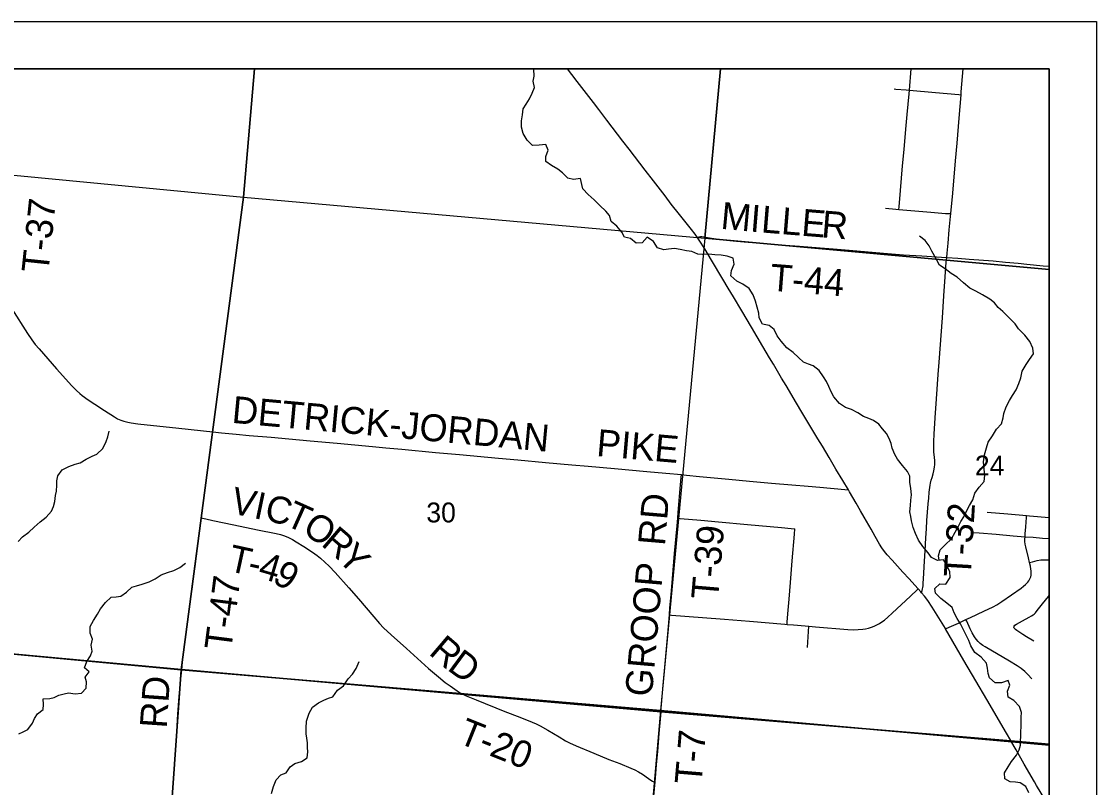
# Model space of a CAD drawing. Extents: x 831 to 1552, y 430 to 870.
# Drawn here: x 1343.42 to 1388.77, y 756.64 to 788.94 of the extents above; entities that cross this region are included whole.
import ezdxf

# ---------------------------------------------------------------- set-up
doc = ezdxf.new("R2010")
doc.units = 0
for name, color, linetype in [('GM_X_Corporation', 7, 'Continuous'), ('GM_X_County_Road', 7, 'Continuous'), ('GM_X_County_Road_Text', 7, 'Continuous'), ('GM_X_Minor_River', 7, 'Continuous'), ('GM_X_Section_Text', 7, 'Continuous'), ('GM_X_Township_Road', 7, 'Continuous'), ('GM_X_Township_Road_Text', 7, 'Continuous'), ('SH_Data', 7, 'Continuous')]:
    doc.layers.add(name, color=color, linetype=linetype)

msp = doc.modelspace()

# ---------------------------------------------------------------- linework, layer by layer
at = {"layer": 'GM_X_Corporation'}
for points in [[(1331.394, 763.348), (1350.173, 761.613), (1362.092, 760.558), (1370.384, 759.825), (1385.154, 758.615), (1386.766, 758.465), (1386.766, 786.938), (1333.549, 786.938)], [(1370.06, 756.136), (1370.131, 756.885), (1370.162, 757.232), (1370.193, 757.593), (1370.242, 758.156), (1370.305, 758.915), (1370.358, 759.522), (1370.384, 759.825), (1362.092, 760.558), (1350.173, 761.613), (1331.394, 763.348)], [(1386.766, 724.317), (1386.766, 758.465), (1385.154, 758.615), (1370.384, 759.825), (1370.358, 759.522), (1370.305, 758.915), (1370.242, 758.156), (1370.193, 757.593), (1370.162, 757.232), (1370.131, 756.885), (1370.06, 756.136)]]:
    msp.add_lwpolyline(points, dxfattribs=at)
for points in [[(1353.25, 786.938), (1333.448, 786.938), (1333.094, 783.414), (1352.786, 781.526)], [(1372.899, 786.938), (1353.25, 786.938), (1352.786, 781.526), (1372.247, 779.801)], [(1386.766, 778.477), (1386.766, 786.938), (1372.899, 786.938), (1372.247, 779.801)], [(1333.094, 783.414), (1352.786, 781.526), (1350.153, 761.603), (1331.382, 763.355)], [(1352.786, 781.526), (1372.247, 779.801), (1370.37, 759.881), (1350.153, 761.603)], [(1386.766, 758.427), (1386.766, 778.477), (1372.247, 779.801), (1370.37, 759.881)], [(1331.382, 763.355), (1350.153, 761.603), (1348.747, 741.721), (1329.567, 743.48)], [(1350.153, 761.603), (1370.37, 759.881), (1368.637, 739.883), (1348.747, 741.721)], [(1386.766, 738.222), (1386.766, 758.427), (1370.37, 759.881), (1368.637, 739.883)]]:
    msp.add_lwpolyline(points, close=True, dxfattribs=at)
at = {"layer": 'GM_X_County_Road'}
for points in [[(1371.924, 779.846), (1371.836, 779.975), (1371.686, 780.174), (1371.179, 780.803), (1370.831, 781.24), (1370.565, 781.583), (1370.074, 782.224), (1369.733, 782.667), (1369.051, 783.552), (1368.785, 783.895), (1368.331, 784.486), (1368.106, 784.783), (1367.767, 785.227), (1367.541, 785.523), (1366.86, 786.41), (1366.634, 786.706), (1366.455, 786.938)], [(1378.3, 769.192), (1378.064, 769.589), (1377.777, 770.07), (1377.483, 770.56), (1377.202, 771.027), (1377.009, 771.346), (1376.338, 772.465), (1376.117, 772.839), (1375.673, 773.586), (1375.482, 773.906), (1375.135, 774.494), (1374.978, 774.762), (1374.692, 775.242), (1374.219, 776.045), (1373.808, 776.74), (1373.453, 777.324), (1373.23, 777.697), (1373.006, 778.07), (1372.532, 778.871), (1372.242, 779.35), (1372.01, 779.718), (1371.924, 779.846)], [(1343.005, 776.829), (1343.673, 775.781), (1343.848, 775.523), (1343.998, 775.324), (1344.158, 775.133), (1344.9, 774.296), (1345.54, 773.58), (1345.733, 773.38), (1345.877, 773.25), (1345.974, 773.172), (1346.227, 772.991), (1346.517, 772.801), (1346.916, 772.535), (1347.339, 772.263), (1347.472, 772.188), (1347.603, 772.129), (1347.731, 772.081), (1347.902, 772.041), (1348.039, 772.014), (1348.33, 771.975), (1350.06, 771.79), (1351.483, 771.637)], [(1351.483, 771.637), (1351.851, 771.598), (1352.47, 771.539), (1353.026, 771.485), (1353.955, 771.407), (1354.698, 771.343), (1355.59, 771.255), (1356.739, 771.154), (1358.224, 771.015), (1358.781, 770.967), (1359.461, 770.905), (1360.884, 770.769), (1361.893, 770.676), (1363.544, 770.527), (1364.349, 770.454), (1365.525, 770.35), (1366.638, 770.25), (1367.32, 770.194), (1368.433, 770.09), (1369.794, 769.967), (1370.596, 769.893), (1371.26, 769.833)], [(1371.26, 769.833), (1371.464, 769.815), (1372.02, 769.759), (1373.256, 769.641), (1374.123, 769.563), (1375.051, 769.479), (1375.917, 769.403), (1376.597, 769.342), (1377.092, 769.3), (1378.144, 769.206), (1378.3, 769.192)], [(1381.244, 765.016), (1381.108, 765.17), (1380.857, 765.445), (1380.603, 765.718), (1380.146, 766.22), (1379.938, 766.451), (1379.823, 766.595), (1379.716, 766.746), (1379.615, 766.902), (1379.426, 767.226), (1379.255, 767.529), (1378.963, 768.045), (1378.813, 768.301), (1378.627, 768.623), (1378.35, 769.109), (1378.3, 769.192)], [(1381.39, 764.849), (1381.355, 764.89), (1381.244, 765.016)], [(1382.398, 763.325), (1382.39, 763.34), (1382.119, 763.8), (1381.836, 764.24), (1381.649, 764.52), (1381.511, 764.704), (1381.39, 764.849)], [(1385.149, 758.621), (1384.967, 758.937), (1384.142, 760.357), (1383.673, 761.141), (1383.176, 762.001), (1382.701, 762.803), (1382.398, 763.325)], [(1386.766, 755.845), (1386.588, 756.15), (1386.242, 756.729), (1386.15, 756.887), (1385.72, 757.622), (1385.375, 758.23), (1385.159, 758.604), (1385.149, 758.621)]]:
    msp.add_lwpolyline(points, dxfattribs=at)
at = {"layer": 'GM_X_Minor_River'}
for points in [[(1369.594, 779.606), (1369.343, 779.594), (1369.11, 779.786), (1368.853, 779.843), (1368.741, 780.049), (1368.532, 780.31), (1368.299, 780.502), (1368.226, 780.754), (1368.061, 780.945), (1367.813, 781.176), (1367.581, 781.422), (1367.317, 781.638), (1367.092, 781.876), (1367.049, 782.066), (1366.999, 782.317), (1366.71, 782.283), (1366.468, 782.339), (1366.242, 782.562), (1366.039, 782.716), (1365.783, 782.863), (1365.542, 783.033), (1365.537, 783.246), (1365.631, 783.511), (1365.535, 783.755), (1365.254, 783.72), (1364.973, 783.708), (1364.748, 783.939), (1364.584, 784.214), (1364.511, 784.48), (1364.514, 784.754), (1364.548, 785.004), (1364.574, 785.262), (1364.705, 785.458), (1364.853, 785.684), (1364.954, 785.918), (1365.064, 786.16), (1365.006, 786.419), (1365.039, 786.639), (1365.035, 786.935), (1365.033, 786.938)], [(1384.19, 761.451), (1384.17, 761.671), (1384.119, 761.885), (1383.902, 762.138), (1383.639, 762.339), (1383.468, 762.615), (1383.379, 762.844), (1383.283, 763.035), (1383.135, 763.318), (1383.023, 763.54), (1382.89, 763.769), (1382.763, 763.999), (1382.675, 764.228), (1382.449, 764.413), (1382.201, 764.606), (1381.969, 764.836), (1381.948, 765.034), (1382.156, 765.229), (1382.414, 765.219), (1382.6, 765.49), (1382.58, 765.749), (1382.424, 766.047), (1382.313, 766.246), (1382.062, 766.211), (1381.805, 766.343), (1381.663, 766.542), (1381.446, 766.796), (1381.252, 767.064), (1381.126, 767.347), (1381.031, 767.598), (1380.958, 767.88), (1380.93, 768.071), (1380.895, 768.269), (1380.913, 768.534), (1380.939, 768.762), (1380.957, 768.975), (1380.93, 769.249), (1380.887, 769.515), (1380.898, 769.766), (1380.787, 769.964), (1380.585, 770.217), (1380.368, 770.486), (1380.256, 770.685), (1380.153, 770.952), (1380.102, 771.143), (1380.014, 771.356), (1379.91, 771.57), (1379.745, 771.762), (1379.581, 771.962), (1379.355, 772.109), (1379.158, 772.194), (1378.939, 772.288), (1378.698, 772.435), (1378.434, 772.583), (1378.184, 772.662), (1377.92, 772.832), (1377.688, 773.116), (1377.577, 773.322), (1377.473, 773.551), (1377.37, 773.757), (1377.25, 773.956), (1377.064, 774.217), (1376.808, 774.417), (1376.611, 774.488), (1376.4, 774.574), (1376.189, 774.774), (1375.972, 774.982), (1375.708, 775.182), (1375.469, 775.458), (1375.297, 775.681), (1375.163, 775.948), (1374.953, 776.125), (1374.68, 776.182), (1374.531, 776.449), (1374.526, 776.639), (1374.446, 776.899), (1374.388, 777.15), (1374.277, 777.409), (1374.113, 777.677), (1373.85, 777.87), (1373.593, 777.987), (1373.338, 778.21), (1373.363, 778.445), (1373.48, 778.702), (1373.445, 778.953), (1373.188, 779.048), (1372.931, 779.089), (1372.665, 779.099), (1372.414, 779.133), (1372.141, 779.121), (1371.943, 779.13), (1371.694, 779.247), (1371.466, 779.265), (1371.201, 779.329), (1370.966, 779.37), (1370.715, 779.342), (1370.517, 779.307), (1370.252, 779.393), (1370.081, 779.661), (1369.817, 779.839), (1369.594, 779.606)], [(1382.133, 766.221), (1382.102, 766.408), (1382.166, 766.666), (1382.389, 766.868), (1382.643, 767.131), (1382.798, 767.403), (1382.946, 767.66), (1383.04, 767.856), (1383.164, 768.06), (1383.273, 768.264), (1383.405, 768.536), (1383.545, 768.77), (1383.639, 769.05), (1383.81, 769.306), (1384.025, 769.539), (1384.051, 769.805), (1384.032, 770.056), (1384.005, 770.367), (1384.039, 770.671), (1384.119, 770.966), (1384.198, 771.201), (1384.376, 771.472), (1384.547, 771.744), (1384.762, 771.969), (1384.834, 772.227), (1384.859, 772.416), (1384.961, 772.689), (1385.101, 772.961), (1385.225, 773.172), (1385.38, 773.406), (1385.49, 773.678), (1385.576, 773.92), (1385.633, 774.2), (1385.804, 774.479), (1385.943, 774.683), (1386.106, 774.932), (1386.078, 775.16), (1385.96, 775.442), (1385.743, 775.711), (1385.48, 775.98), (1385.331, 776.194), (1385.068, 776.455), (1384.813, 776.709), (1384.618, 776.878), (1384.461, 777.078), (1384.265, 777.224), (1383.956, 777.41), (1383.677, 777.573), (1383.42, 777.698), (1383.157, 777.913), (1382.894, 778.152), (1382.638, 778.314), (1382.389, 778.507), (1382.148, 778.662), (1382.007, 778.937), (1381.821, 779.251), (1381.702, 779.48), (1381.538, 779.71), (1381.297, 779.887)], [(1343.28, 767.014), (1343.465, 767.209), (1343.726, 767.404), (1343.957, 767.622), (1344.202, 767.839), (1344.463, 768.034), (1344.687, 768.297), (1344.765, 768.493), (1344.821, 768.706), (1344.854, 768.948), (1344.895, 769.138), (1344.913, 769.388), (1344.916, 769.578), (1344.948, 769.775), (1345.141, 770.031), (1345.417, 770.18), (1345.676, 770.268), (1345.89, 770.334), (1346.142, 770.483), (1346.402, 770.609), (1346.601, 770.698), (1346.847, 770.931), (1346.995, 771.225), (1347.058, 771.422), (1347.114, 771.665)], [(1343.3, 758.897), (1343.491, 758.986), (1343.69, 759.083), (1343.883, 759.354), (1343.969, 759.551), (1344.093, 759.754), (1344.331, 759.934), (1344.349, 760.139), (1344.337, 760.382), (1344.61, 760.387), (1344.801, 760.43), (1345, 760.534), (1345.213, 760.585), (1345.404, 760.636), (1345.684, 760.587), (1345.943, 760.614), (1346.15, 760.824), (1346.154, 761.098), (1346.111, 761.289), (1346.273, 761.515), (1346.078, 761.692), (1346.172, 761.957), (1346.335, 762.19), (1346.406, 762.387), (1346.363, 762.638), (1346.412, 762.889), (1346.316, 763.148), (1346.32, 763.429), (1346.46, 763.686), (1346.63, 763.95), (1346.755, 764.177), (1346.963, 764.44), (1347.202, 764.665), (1347.414, 764.678), (1347.605, 764.706), (1347.842, 764.871), (1348.073, 765.081), (1348.264, 765.139), (1348.515, 765.22), (1348.797, 765.308), (1349.057, 765.441), (1349.31, 765.606), (1349.577, 765.709), (1349.844, 765.797), (1350.104, 765.923), (1350.342, 766.095)], [(1353.965, 756.392), (1354.052, 756.68), (1354.162, 756.96), (1354.355, 757.17), (1354.584, 757.259), (1354.754, 757.508), (1354.954, 757.65), (1355.228, 757.738), (1355.473, 757.895), (1355.499, 758.138), (1355.486, 758.328), (1355.481, 758.518), (1355.461, 758.716), (1355.425, 758.906), (1355.421, 759.142), (1355.447, 759.431), (1355.558, 759.771), (1355.698, 760.028), (1355.951, 760.215), (1356.172, 760.327), (1356.363, 760.408), (1356.554, 760.459), (1356.755, 760.738), (1357.001, 760.925), (1357.202, 761.219), (1357.379, 761.415), (1357.542, 761.664), (1357.659, 761.959)], [(1385.912, 756.42), (1385.786, 756.68), (1385.545, 756.843), (1385.355, 756.86), (1385.12, 756.878), (1384.893, 757.01), (1384.881, 757.253), (1385.037, 757.518), (1385.184, 757.737), (1385.385, 758), (1385.509, 758.227), (1385.557, 758.432), (1385.579, 758.979), (1385.59, 759.222), (1385.585, 759.412), (1385.595, 759.61), (1385.597, 759.8), (1385.525, 760.059), (1385.277, 760.305), (1385.043, 760.452), (1385.009, 760.704), (1385.11, 760.953), (1385.037, 761.152), (1384.762, 761.056), (1384.496, 761.052), (1384.248, 761.26), (1384.19, 761.451)]]:
    msp.add_lwpolyline(points, dxfattribs=at)
at = {"layer": 'GM_X_Township_Road'}
for p, q in [((1380.871, 786.04), (1380.951, 786.938)), ((1376.573, 762.539), (1376.638, 763.444)), ((1370.064, 756.126), (1370.135, 756.874))]:
    msp.add_line(p, q, dxfattribs=at)
for points in [[(1383.052, 785.85), (1383.062, 785.977), (1383.148, 786.938)], [(1380.238, 786.096), (1380.3, 786.092), (1380.733, 786.052), (1380.871, 786.04)], [(1380.432, 781.012), (1380.442, 781.126), (1380.499, 781.806), (1380.588, 782.856), (1380.652, 783.536), (1380.727, 784.401), (1380.786, 785.018), (1380.857, 785.884), (1380.871, 786.04)], [(1380.871, 786.04), (1381.971, 785.947), (1382.961, 785.858), (1383.052, 785.85)], [(1382.62, 780.838), (1382.7, 781.703), (1382.817, 783.065), (1382.885, 783.808), (1382.971, 784.862), (1383.052, 785.85)], [(1379.87, 781.068), (1380.299, 781.023), (1380.432, 781.012)], [(1380.432, 781.012), (1381.78, 780.901), (1382.397, 780.849), (1382.521, 780.843), (1382.62, 780.838)], [(1382.448, 778.99), (1382.464, 779.166), (1382.509, 779.598), (1382.558, 780.156), (1382.608, 780.713), (1382.62, 780.838)], [(1371.924, 779.846), (1371.994, 779.86), (1372.06, 779.873), (1372.116, 779.87), (1372.532, 779.8), (1373.024, 779.739), (1373.58, 779.678), (1374.074, 779.632), (1374.63, 779.585), (1375.186, 779.54), (1375.434, 779.52), (1376.238, 779.461), (1377.105, 779.394), (1377.662, 779.35), (1378.159, 779.311), (1379.952, 779.158), (1380.631, 779.105), (1381.405, 779.051), (1382.23, 779.005), (1382.448, 778.99)], [(1381.39, 764.849), (1381.415, 764.953), (1381.431, 765.021), (1381.44, 765.067), (1381.45, 765.142), (1381.455, 765.25), (1381.466, 765.44), (1381.506, 766.184), (1381.534, 766.615), (1381.568, 767.172), (1381.588, 767.55), (1381.609, 767.896), (1381.663, 768.596), (1381.687, 768.841), (1381.712, 769.087), (1381.75, 769.385), (1381.766, 769.47), (1381.796, 769.601), (1381.827, 769.713), (1381.871, 769.868), (1381.903, 769.999), (1381.918, 770.064), (1381.932, 770.156), (1381.942, 770.242), (1381.945, 770.306), (1381.942, 770.432), (1381.929, 770.557), (1381.905, 770.799), (1381.902, 770.984), (1381.903, 771.232), (1381.92, 771.541), (1381.966, 772.223), (1382.016, 773.03), (1382.087, 774.048), (1382.132, 774.579), (1382.269, 776.438), (1382.331, 777.369), (1382.383, 778.175), (1382.43, 778.795), (1382.448, 778.99)], [(1382.448, 778.99), (1382.914, 778.959), (1383.4, 778.923), (1384.403, 778.84), (1384.926, 778.794), (1385.459, 778.744), (1385.83, 778.707), (1386.51, 778.643), (1386.766, 778.617)], [(1351.008, 768.01), (1351.093, 768.668), (1351.277, 770.081), (1351.407, 771.063), (1351.455, 771.426), (1351.477, 771.594), (1351.483, 771.637)], [(1371.1, 767.996), (1371.122, 768.234), (1371.181, 768.913), (1371.221, 769.408), (1371.249, 769.716), (1371.26, 769.833)], [(1384.151, 768.249), (1385.024, 768.174), (1385.82, 768.103)], [(1350.177, 761.602), (1350.214, 761.93), (1350.335, 762.895), (1350.548, 764.492), (1350.628, 765.106), (1350.675, 765.474), (1350.738, 765.966), (1350.794, 766.395), (1350.87, 766.948), (1350.95, 767.562), (1351.008, 768.01)], [(1351.008, 768.01), (1351.048, 768.002), (1351.189, 767.974), (1351.49, 767.904), (1351.974, 767.794), (1352.642, 767.654), (1353.371, 767.509), (1354.161, 767.349), (1354.341, 767.306), (1354.516, 767.249), (1354.686, 767.177), (1354.851, 767.094), (1355.012, 767.002), (1355.327, 766.805), (1355.689, 766.567), (1355.891, 766.425), (1356.035, 766.31), (1356.22, 766.145), (1356.396, 765.972), (1356.65, 765.701), (1357.229, 765.055), (1357.641, 764.592), (1358.278, 763.832), (1358.524, 763.551), (1358.696, 763.372), (1359.013, 763.075), (1359.661, 762.497), (1360.581, 761.665), (1361.006, 761.303), (1361.297, 761.07), (1361.498, 760.923), (1361.798, 760.716), (1361.926, 760.634), (1362.002, 760.594), (1362.096, 760.548)], [(1370.749, 763.92), (1370.774, 764.217), (1370.824, 764.773), (1370.885, 765.452), (1370.969, 766.504), (1371.071, 767.678), (1371.1, 767.996)], [(1371.1, 767.996), (1371.206, 767.986), (1372.073, 767.912), (1372.814, 767.841), (1374.05, 767.727), (1375.473, 767.597), (1375.884, 767.561), (1376.041, 767.548)], [(1385.752, 767.215), (1385.762, 767.343), (1385.785, 767.629), (1385.815, 768.032), (1385.82, 768.103)], [(1385.82, 768.103), (1385.946, 768.091), (1386.766, 768.024)], [(1375.716, 763.519), (1375.722, 763.608), (1375.748, 763.958), (1375.8, 764.579), (1375.855, 765.278), (1375.931, 766.205), (1376.025, 767.318), (1376.041, 767.548)], [(1383.54, 767.396), (1383.819, 767.373), (1384.538, 767.317), (1385.257, 767.255), (1385.752, 767.215)], [(1385.945, 766.132), (1385.903, 766.319), (1385.789, 766.782), (1385.762, 766.903), (1385.746, 767.008), (1385.746, 767.11), (1385.752, 767.215)], [(1385.752, 767.215), (1386.094, 767.192), (1386.494, 767.159), (1386.766, 767.138)], [(1383.26, 763.724), (1383.449, 763.813), (1384.01, 764.071), (1384.403, 764.258), (1384.565, 764.348), (1384.774, 764.481), (1385.587, 765.046), (1385.686, 765.123), (1385.778, 765.207), (1385.825, 765.253), (1385.867, 765.305), (1385.907, 765.354), (1385.946, 765.413), (1385.969, 765.466), (1385.992, 765.528), (1386.005, 765.591), (1386.008, 765.646), (1386.008, 765.719), (1386.008, 765.778), (1386.002, 765.85), (1385.982, 765.968), (1385.945, 766.132)], [(1385.945, 766.132), (1386.064, 766.162), (1386.261, 766.211), (1386.422, 766.237), (1386.543, 766.244), (1386.714, 766.24), (1386.766, 766.237)], [(1376.638, 763.444), (1376.914, 763.421), (1378.279, 763.308), (1378.529, 763.294), (1378.717, 763.297), (1378.904, 763.313), (1379.028, 763.333), (1379.151, 763.363), (1379.27, 763.402), (1379.387, 763.448), (1379.501, 763.502), (1379.611, 763.562), (1379.717, 763.63), (1379.819, 763.703), (1379.963, 763.823), (1380.148, 763.991), (1380.917, 764.715), (1381.199, 764.975), (1381.244, 765.016)], [(1386.127, 762.811), (1385.817, 762.987), (1385.657, 763.087), (1385.4, 763.265), (1385.349, 763.304), (1385.295, 763.365), (1385.286, 763.395), (1385.293, 763.438), (1385.322, 763.484), (1385.398, 763.533), (1385.647, 763.667), (1385.923, 763.822), (1386.031, 763.881), (1386.094, 763.917), (1386.14, 763.956), (1386.186, 764.002), (1386.268, 764.107), (1386.494, 764.389), (1386.737, 764.701), (1386.766, 764.738)], [(1370.389, 759.814), (1370.49, 760.949), (1370.574, 761.876), (1370.681, 763.112), (1370.749, 763.92)], [(1370.749, 763.92), (1370.836, 763.913), (1372.139, 763.809), (1373.069, 763.733), (1374.124, 763.649), (1375.612, 763.528), (1375.716, 763.519)], [(1382.398, 763.325), (1382.551, 763.395), (1382.945, 763.576), (1383.26, 763.724)], [(1386.035, 761.222), (1385.869, 761.411), (1385.747, 761.529), (1385.593, 761.661), (1385.424, 761.773), (1385.1, 761.968), (1384.075, 762.567), (1383.972, 762.634), (1383.861, 762.716), (1383.772, 762.801), (1383.692, 762.895), (1383.62, 762.995), (1383.524, 763.163), (1383.437, 763.329), (1383.293, 763.65), (1383.26, 763.724)], [(1375.716, 763.519), (1375.984, 763.496), (1376.48, 763.457), (1376.638, 763.444)], [(1349.801, 756.507), (1349.846, 757.189), (1349.886, 757.81), (1349.937, 758.554), (1349.983, 759.236), (1350.017, 759.732), (1350.07, 760.476), (1350.122, 761.096), (1350.177, 761.602)], [(1362.096, 760.548), (1362.173, 760.512), (1362.314, 760.45), (1362.595, 760.332), (1363.806, 759.847), (1364.444, 759.602), (1364.965, 759.402), (1365.135, 759.328), (1365.3, 759.245), (1365.625, 759.064), (1366.102, 758.773), (1366.37, 758.614), (1366.535, 758.527), (1366.819, 758.397), (1367.564, 758.087), (1368.196, 757.826), (1368.659, 757.646), (1369.12, 757.462), (1369.289, 757.385), (1369.452, 757.298), (1369.608, 757.2), (1369.861, 757.019), (1369.966, 756.951), (1370.03, 756.914), (1370.068, 756.895), (1370.102, 756.882), (1370.135, 756.874)], [(1370.135, 756.874), (1370.166, 757.221), (1370.198, 757.582), (1370.247, 758.145), (1370.31, 758.904), (1370.363, 759.512), (1370.389, 759.814)]]:
    msp.add_lwpolyline(points, dxfattribs=at)
at = {"layer": 'SH_Data'}
for p, q in [((1248.766, 788.938), (1388.766, 788.938)), ((1388.766, 788.938), (1388.766, 648.938)), ((1250.766, 786.938), (1386.766, 786.938)), ((1386.766, 786.938), (1386.766, 650.938))]:
    msp.add_line(p, q, dxfattribs=at)

# ---------------------------------------------------------------- texts
at = {"layer": 'GM_X_County_Road_Text'}
for s, height, rotation, p in [('DETRICK-JORDAN', 1.13636, 354.7624, (1352.263, 772.02)), ('PIKE', 1.1364, 355.0567, (1367.646, 770.62))]:
    msp.add_text(s, height=height, rotation=rotation, dxfattribs=at).set_placement(p)
at = {"layer": 'GM_X_Section_Text'}
for s, p in [('24', (1383.637, 769.799)), ('30', (1360.496, 767.818))]:
    msp.add_text(s, height=0.8371, rotation=0, dxfattribs=at).set_placement(p)
at = {"layer": 'GM_X_Township_Road_Text'}
for s, height, rotation, p in [('T-37', 1.1364, 84.0115, (1344.549, 778.305)), ('M', 1.136, 354.67, (1372.887, 780.201)), ('I', 1.136, 355.3686, (1374.13, 780.085)), ('L', 1.136, 355.3535, (1374.595, 780.047)), ('L', 1.136, 355.3535, (1375.443, 779.978)), ('E', 1.136, 355.3535, (1376.29, 779.91)), ('R', 1.136, 355.3564, (1377.137, 779.841)), ('T-44', 1.1364, 355.5221, (1374.966, 777.592)), ('V', 1.136, 348.1978, (1352.195, 768.213)), ('I', 1.136, 348.168, (1353.174, 768.008)), ('C', 1.136, 347.2011, (1353.626, 767.914)), ('T', 1.136, 335.8965, (1354.48, 767.726)), ('RD', 1.1364, 85.1131, (1370.558, 766.811)), ('T-32', 1.1364, 86.5979, (1383.457, 765.488)), ('O', 1.136, 326.5403, (1355.213, 767.402)), ('R', 1.136, 319.5778, (1356.018, 766.873)), ('T-39', 1.1364, 85.0756, (1372.797, 764.537)), ('T', 1.136, 347.6781, (1352.083, 765.781)), ('Y', 1.136, 313.1064, (1356.704, 766.291)), ('4', 1.136, 343.5435, (1353.349, 765.505)), ('-', 1.136, 347.6016, (1352.913, 765.6)), ('9', 1.136, 327.8573, (1353.945, 765.341)), ('GROOP', 1.1364, 84.9678, (1370.008, 760.444)), ('T-47', 1.1364, 82.6601, (1352.26, 762.39)), ('R', 1.136, 319.5088, (1360.559, 762.285)), ('D', 1.136, 323.5953, (1361.337, 761.625)), ('RD', 1.1364, 86.0508, (1349.541, 759.116)), ('T-20', 1.1364, 338.2081, (1361.776, 758.542)), ('T-7', 1.1364, 85.2348, (1372.102, 756.746))]:
    msp.add_text(s, height=height, rotation=rotation, dxfattribs=at).set_placement(p)

doc.saveas('drawing.dxf')
